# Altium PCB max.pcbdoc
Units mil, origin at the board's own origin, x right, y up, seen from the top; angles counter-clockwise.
Board outline 951.1 x 570.6 mil, 2 copper layers (Top Layer, Bottom Layer), stack 62.2 mil thick; 9 components, 9 nets, 24 pads, 4 vias.
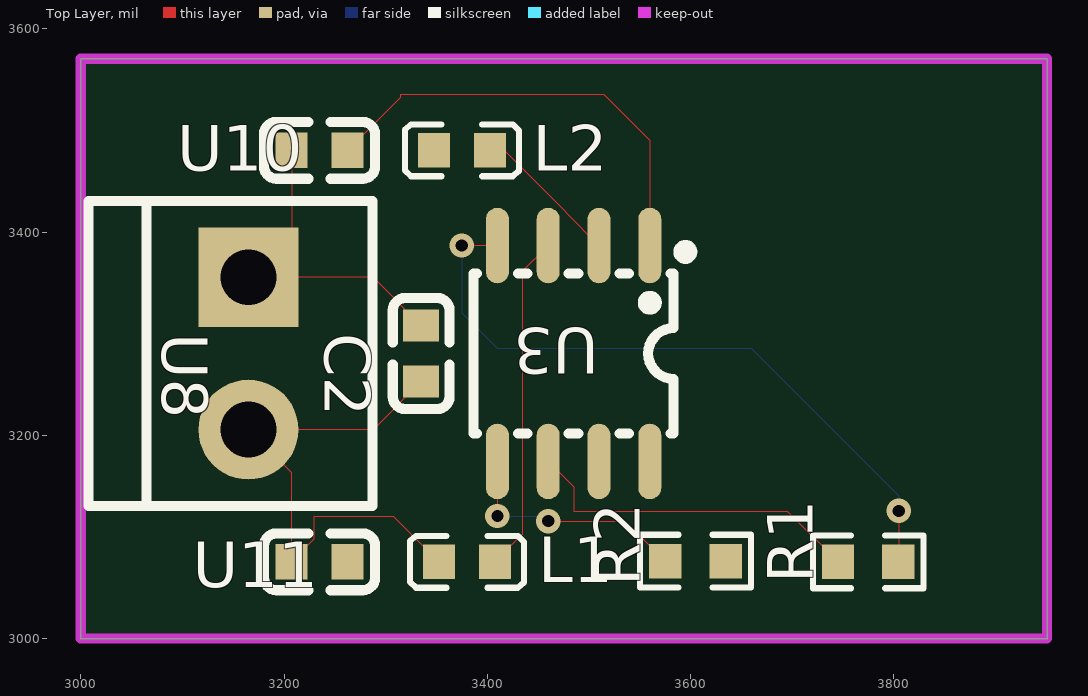
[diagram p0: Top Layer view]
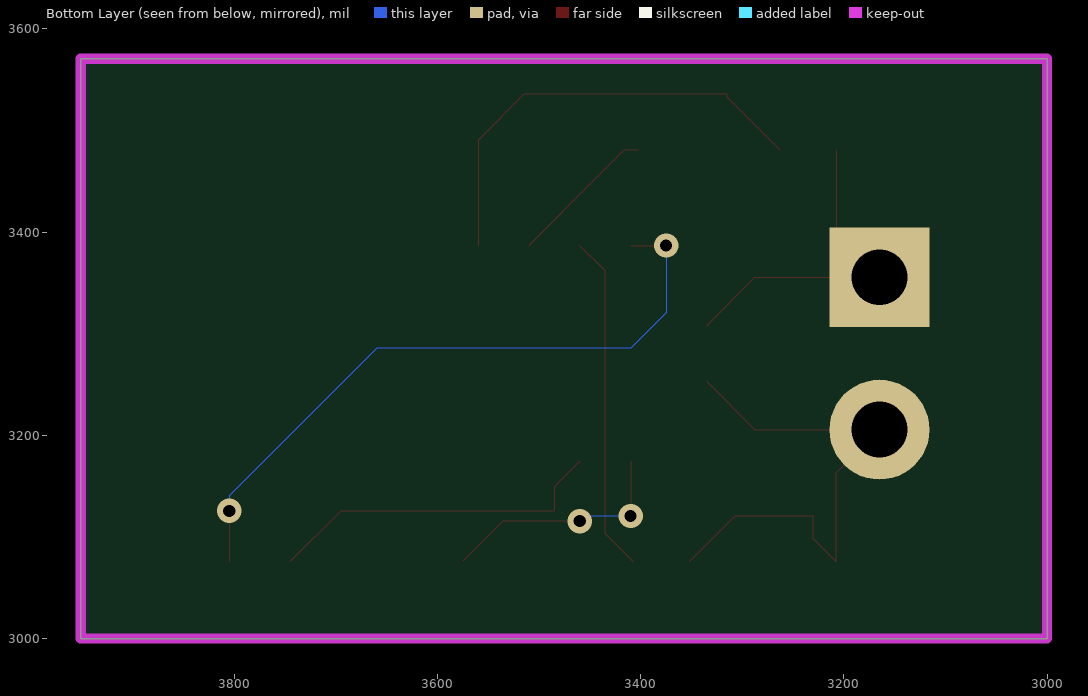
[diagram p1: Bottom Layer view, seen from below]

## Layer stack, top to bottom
Top Solder Mask Layer: solder mask 0.4, Dk 3.3
Top Layer: signal copper 1.4
Dielectric1: surface 59.4, FR4, Dk 4.5
Bottom Layer: signal copper 1.4
Bottom Solder Mask Layer: solder mask 0.4, Dk 3.3

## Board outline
3000,3570.6 3000,3000 3951.1,3000 3951.1,3570.6

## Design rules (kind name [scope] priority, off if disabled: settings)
BoardOutlineClearance safeClearance [All] p0: genericclearance=10 ignorepadtopadclearanceinfootprint=FALSE except(0: Arc-SplitContinuation Track-SplitContinuation SMDPad-SplitContinuation THPad-SplitContinuation Via-SplitContinuation Fill-SplitContinuation Poly-SplitContinuation Region-SplitContinuation Text-SplitContinuation)
BoardOutlineClearance Plane_innerPlane [All] p0: genericclearance=10 ignorepadtopadclearanceinfootprint=FALSE except(0: Arc-SplitContinuation Track-SplitContinuation SMDPad-SplitContinuation THPad-SplitContinuation Via-SplitContinuation Fill-SplitContinuation Poly-SplitContinuation Region-SplitContinuation Text-SplitContinuation)
BoardOutlineClearance Copper_CopperRegion [All] p0: genericclearance=10 ignorepadtopadclearanceinfootprint=FALSE except(0: Arc-SplitContinuation Track-SplitContinuation SMDPad-SplitContinuation THPad-SplitContinuation Via-SplitContinuation Fill-SplitContinuation Poly-SplitContinuation Region-SplitContinuation Text-SplitContinuation)
BoardOutlineClearance Copper_CopperRegion1 [All] p0: genericclearance=10 ignorepadtopadclearanceinfootprint=FALSE except(0: Arc-SplitContinuation Track-SplitContinuation SMDPad-SplitContinuation THPad-SplitContinuation Via-SplitContinuation Fill-SplitContinuation Poly-SplitContinuation Region-SplitContinuation Text-SplitContinuation)
BoardOutlineClearance otherClearance [All] p0: genericclearance=10 ignorepadtopadclearanceinfootprint=FALSE except(0: Arc-SplitContinuation Track-SplitContinuation SMDPad-SplitContinuation THPad-SplitContinuation Via-SplitContinuation Fill-SplitContinuation Poly-SplitContinuation Region-SplitContinuation Text-SplitContinuation)
Clearance safeClearance [All] p1: gap=7 ignorepadtopadclearanceinfootprint=FALSE
Clearance Plane_innerPlane [All] p1: gap=7 ignorepadtopadclearanceinfootprint=FALSE
Clearance Copper_CopperRegion [All] p1: gap=7 ignorepadtopadclearanceinfootprint=FALSE
Clearance Copper_CopperRegion1 [All] p1: gap=7 ignorepadtopadclearanceinfootprint=FALSE
Clearance otherClearance [All] p1: gap=7 ignorepadtopadclearanceinfootprint=FALSE
DiffPairsRouting differentialPair [All] p1: maxuncoupledlength=10 minlimit=6 maxlimit=Infinity mostfreqgap=6 toplayer_minwidth=5 toplayer_prefwidth=10 toplayer_maxwidth=100 bottomlayer_minwidth=5 bottomlayer_prefwidth=10 bottomlayer_maxwidth=100
PasteMaskExpansion Common [All] p1: expansion=0
PlaneConnect innerPlane [All] p1: planeconnectstyle=Relief reliefexpansion=20 reliefentries=4 reliefconductorwidth=10 reliefairgap=10
PolygonConnect CopperRegion [All] p1: connectstyle=Relief reliefentries=4 reliefconductorwidth=0 polygonreliefangle="90 Angle" airgapwidth=1
PolygonConnect CopperRegion1 [All] p1: connectstyle=Relief reliefentries=4 reliefconductorwidth=0 polygonreliefangle="90 Angle" airgapwidth=1
RoutingVias viaSize [All] p1: viastyle="Through Hole" holewidth=13.7796 minholewidth=13.7796 maxholewidth=78.7402 width=13.7796 minwidth=13.7796 maxwidth=78.7402
RoutingVias default [All] p1: viastyle="Through Hole" holewidth=12.0078 minholewidth=11.811 maxholewidth=248.0316 width=12.0078 minwidth=11.811 maxwidth=248.0316
SolderMaskExpansion Common [All] p1: useseparateexpansions=TRUE expansion=0 expansionbottom=0
Width trackWidth [All] p1: maxlimit=100 minlimit=8 preferedwidth=8
Width default [All] p1: maxlimit=100 minlimit=0 preferedwidth=0

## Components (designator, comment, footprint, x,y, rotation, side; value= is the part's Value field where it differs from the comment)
C2 "10nF" C0603#1 3335,3280.6 r270 top
L1 "BLM18AG601SN1D" L0603 3380,3075.6 r0 top
L2 "BLM18AG601SN1D" L0603 3375,3480.6 r0 top
R1 "10kΩ" R0603 3775,3075.6 r0 top
R2 "10kΩ" R0603 3605,3076.2 r0 top
U3 "MAX31855KASA+T" SO-8_L4.9-W3.9-P1.27-LS5.9-BL 3485,3280.6 r180 top
U8 "XY340V-3.81-2P" CONN-TH_XY340V-3.81-2P 3165,3280.6 r270 top
U10 "100nF" C0603#2 3235,3480.6 r0 top
U11 "100nF" C0603#2 3235,3075.6 r0 top

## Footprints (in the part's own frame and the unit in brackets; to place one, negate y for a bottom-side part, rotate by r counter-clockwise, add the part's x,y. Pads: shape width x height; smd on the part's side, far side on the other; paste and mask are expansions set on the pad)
C0603#1 [mil]
  rect 31.5x35.4 smd: 1(-27.5,0) 2(27.6,0)
  silkscreen extent -55,-28 55,28
C0603#2 [mil]
  rect 31.5x35.4 smd: 1(-27.6,0) 2(27.6,0)
  silkscreen extent -55,-28 55,28
CONN-TH_XY340V-3.81-2P [mil]
  rect 98.4x98.4 hole 55.1: 1(-75,0)
  round 98.4 hole 55.1: 2(75,0)
  silkscreen extent -150,-158 150,122
L0603 [mil]
  rect 31.5x34 smd paste-3937 mask+2: 1(-27.6,0) 2(27.6,0)
  silkscreen extent -56,-26 56,26
R0603 [mil]
  rect 31.8x34 smd paste-3937 mask+2: 1(-29.7,0) 2(29.7,0)
  silkscreen extent -54,-26 54,26
SO-8_L4.9-W3.9-P1.27-LS5.9-BL [mm]
  oval 0.574x1.887 smd: 1(-1.905,-2.697) 2(-0.635,-2.697) 3(0.635,-2.697) 4(1.905,-2.697) 5(1.905,2.7) 6(0.635,2.7) 7(-0.635,2.7) 8(-1.905,2.7)
  silkscreen extent -2.94,-2.69 2.5,2

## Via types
v1: diameter 24, hole 12, Top Layer to Bottom Layer, 4 vias

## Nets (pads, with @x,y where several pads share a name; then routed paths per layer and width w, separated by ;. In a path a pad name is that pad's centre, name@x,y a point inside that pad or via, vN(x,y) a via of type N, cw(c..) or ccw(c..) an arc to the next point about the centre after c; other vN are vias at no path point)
$1N236: C2.2 L1.1 U8.2 U11.1 | length 532.5
  Top Layer w0.1: 3230,3120.6 3230,3098.1 U11.1 3207.4,3163.1 U8.2 3287.6,3205.6 C2.2 ; 3230.1,3120.6 3307.4,3120.6 L1.1
$1N237: C2.1 L2.1 U8.1 U10.1 | length 332.3
  Top Layer w0.1: U10.1 3207.4,3398 U8.1 3287.6,3355.6 C2.1
$1N244: L1.2 U3.3 | length 332.9
  Top Layer w0.1: L1.2 3435,3103 3435,3361.8 U3.3
$1N245: L2.2 U3.2 | length 146.5
  Top Layer w0.1: L2.2 3416.7,3480.6 3477.3,3419.9 3477.3,3419.5 U3.2
CS: R1.1 U3.6 | length 339.9
  Top Layer w0.1: U3.6 3485,3149.3 3485,3125.6 ; 3485.1,3125.5 3695.4,3125.5 R1.1
GND: R2.2 U3.1 U10.2 U11.2 | length 444
  Top Layer w0.1: U10.2 3315,3533 3315,3535.6 ; 3315.1,3535.6 3514.9,3535.6 3560,3490.6 U3.1
SCK: R2.1 U3.5 | length 237.4
  Top Layer w0.1: v1(3410,3120.6) U3.5 ; v1(3460,3115.6) 3536,3115.6 R2.1
  Bottom Layer w0.1: v1(3410,3120.6) 3455,3120.6 v1(3460,3115.6)
SO: U3.7
VCC: R1.2 U3.4 | length 670.9
  Top Layer w0.1: v1(3375,3386.8) U3.4 ; R1.2 3805,3075.9 v1(3805,3125.6)
  Bottom Layer w0.1: v1(3375,3386.8) 3375,3320.6 3410,3285.6 3660,3285.6 3805,3140.6 v1(3805,3125.6)
pads on no net: U3.8

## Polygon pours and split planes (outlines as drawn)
GND on Top Layer (solid, remove dead copper, pour order 0): 3000,3570.6 3000,3000 3951.1,3000 3951.1,3570.6

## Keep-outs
Board Outline Layer:
  the board outline again, w10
